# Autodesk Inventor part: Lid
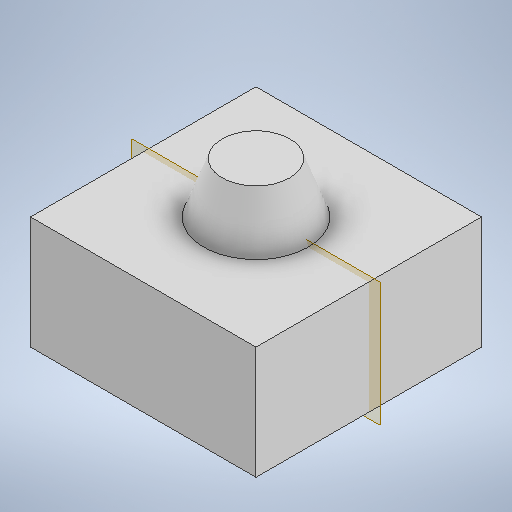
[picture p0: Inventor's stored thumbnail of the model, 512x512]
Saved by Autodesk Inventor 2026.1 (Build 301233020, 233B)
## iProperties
Created: 2026-11
Part Number: Lid
Material: Generic
Document SubType Name: Modeling
Designer: hp
Density: 1 g/cm^3
Appearance: Default
Author: hp
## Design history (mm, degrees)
sketch "Sketch1"
  geometry: L1 (-20, 20)-(20, 20); L2 (20, 20)-(20, -20); L3 (20, -20)-(-20, -20); L4 (-20, -20)-(-20, 20); L5 (-20, 20)-(20, -20); L6 (20, 20)-(-20, -20); 1 further point
  constraints: 12 end point, 2 midpoint, 2 parallel, 1 horizontal, 1 perpendicular
  dimensions: "d0" = 40 distance of L2.end L3.end; "d1" = 40 distance of L1.end L2.end
extrude "Extrusion1" new body sketch "Sketch1" distance "d2" = 20; taper "d3" = 0 deg
workplane "Work Plane1"
sketch "Sketch2"
  geometry: L1 (20, 0)-(20, 20); L2 (40, 20)-(0, 20) reference; L3 (20, 20)-(20, 29); L4 (20, 29)-(26, 29); L5 (26, 29)-(29.276, 20); L6 (20, 20)-(29.276, 20)
  constraints: 10 end point, 1 midpoint, 1 parallel, 1 perpendicular, 1 point on line, 1 vertical
  dimensions: "d4" = 9 distance of L1.end L3.end; "d5" = 6 distance of L3.end L4.end; "d6" = 110 deg angle of L5 L4
revolve "Revolution1" sketch "Sketch2" stored, may be unused: angle "d7" = 90 deg
body "Solid1"
